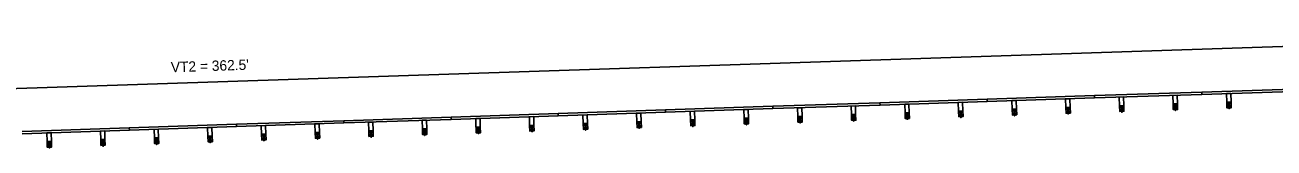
# Model space of a CAD drawing. Extents: x 16537443 to 16538473, y 7054586 to 7055469.
# Drawn here: x 16537667.3 to 16537812.8, y 7054595.8 to 7054610.2 of the extents above; entities that cross this region are included whole.
import ezdxf

# ---------------------------------------------------------------- set-up
doc = ezdxf.new("R2010")
doc.units = 0
doc.layers.add('Draft_DNC', color=7, linetype='Continuous')

msp = doc.modelspace()

# ---------------------------------------------------------------- linework, layer by layer
at = {"layer": 'Draft_DNC'}
for p, q in [((16537888.55, 7054610.16), (16537526.25, 7054598.08)), ((16537779.4, 7054601.52), (16537766.91, 7054601.11)), ((16537791.9, 7054601.94), (16537779.4, 7054601.52)), ((16537779.4, 7054601.52), (16537779.41, 7054601.25)), ((16537779.4, 7054601.52), (16537779.41, 7054601.25)), ((16537791.91, 7054601.67), (16537779.41, 7054601.25)), ((16537782.29, 7054601.35), (16537782.79, 7054601.36)), ((16537782.32, 7054600.35), (16537782.29, 7054601.35)), ((16537782.79, 7054601.36), (16537782.82, 7054600.36)), ((16537788.53, 7054601.56), (16537789.03, 7054601.57)), ((16537788.57, 7054600.55), (16537788.53, 7054601.56)), ((16537789.03, 7054601.57), (16537789.07, 7054600.57)), ((16537804.39, 7054602.35), (16537791.9, 7054601.94)), ((16537791.9, 7054601.94), (16537791.91, 7054601.67)), ((16537791.9, 7054601.94), (16537791.91, 7054601.67)), ((16537804.4, 7054602.08), (16537791.91, 7054601.67)), ((16537794.78, 7054601.76), (16537795.28, 7054601.78)), ((16537794.81, 7054600.76), (16537794.78, 7054601.76)), ((16537795.28, 7054601.78), (16537795.31, 7054600.78)), ((16537801.03, 7054601.97), (16537801.53, 7054601.99)), ((16537801.06, 7054600.97), (16537801.03, 7054601.97)), ((16537801.53, 7054601.99), (16537801.56, 7054600.99)), ((16537816.88, 7054602.77), (16537804.39, 7054602.35)), ((16537804.39, 7054602.35), (16537804.4, 7054602.08)), ((16537804.39, 7054602.35), (16537804.4, 7054602.08)), ((16537816.89, 7054602.5), (16537804.4, 7054602.08)), ((16537807.27, 7054602.18), (16537807.77, 7054602.2)), ((16537807.31, 7054601.18), (16537807.27, 7054602.18)), ((16537807.77, 7054602.2), (16537807.81, 7054601.2)), ((16537741.93, 7054600.27), (16537729.43, 7054599.86)), ((16537741.93, 7054600), (16537729.44, 7054599.58)), ((16537738.56, 7054599.89), (16537739.06, 7054599.91)), ((16537738.59, 7054598.89), (16537738.56, 7054599.89)), ((16537739.06, 7054599.91), (16537739.09, 7054598.91)), ((16537754.42, 7054600.69), (16537741.93, 7054600.27)), ((16537754.43, 7054600.42), (16537741.93, 7054600)), ((16537741.93, 7054600.27), (16537741.93, 7054600)), ((16537741.93, 7054600.27), (16537741.93, 7054600)), ((16537744.81, 7054600.1), (16537745.31, 7054600.11)), ((16537744.84, 7054599.1), (16537744.81, 7054600.1)), ((16537745.31, 7054600.11), (16537745.34, 7054599.11)), ((16537751.05, 7054600.31), (16537751.55, 7054600.32)), ((16537751.09, 7054599.31), (16537751.05, 7054600.31)), ((16537751.55, 7054600.32), (16537751.59, 7054599.32)), ((16537766.91, 7054601.11), (16537754.42, 7054600.69)), ((16537754.42, 7054600.69), (16537754.43, 7054600.42)), ((16537754.42, 7054600.69), (16537754.43, 7054600.42)), ((16537766.92, 7054600.83), (16537754.43, 7054600.42)), ((16537757.3, 7054600.51), (16537757.8, 7054600.53)), ((16537757.33, 7054599.51), (16537757.3, 7054600.51)), ((16537757.8, 7054600.53), (16537757.83, 7054599.53)), ((16537763.55, 7054600.72), (16537764.05, 7054600.74)), ((16537763.58, 7054599.72), (16537763.55, 7054600.72)), ((16537764.05, 7054600.74), (16537764.08, 7054599.74)), ((16537766.91, 7054601.11), (16537766.92, 7054600.83)), ((16537766.91, 7054601.11), (16537766.92, 7054600.83)), ((16537779.41, 7054601.25), (16537766.92, 7054600.83)), ((16537769.79, 7054600.93), (16537770.29, 7054600.95)), ((16537769.83, 7054599.93), (16537769.79, 7054600.93)), ((16537770.33, 7054599.95), (16537769.83, 7054599.93)), ((16537770.35, 7054599.28), (16537769.83, 7054599.93)), ((16537769.85, 7054599.26), (16537770.33, 7054599.95)), ((16537770.08, 7054599.94), (16537770.1, 7054599.27)), ((16537770.29, 7054600.95), (16537770.33, 7054599.95)), ((16537776.04, 7054601.14), (16537776.54, 7054601.16)), ((16537776.07, 7054600.14), (16537776.04, 7054601.14)), ((16537776.57, 7054600.15), (16537776.07, 7054600.14)), ((16537776.6, 7054599.49), (16537776.07, 7054600.14)), ((16537776.1, 7054599.47), (16537776.57, 7054600.15)), ((16537776.32, 7054600.15), (16537776.35, 7054599.48)), ((16537776.54, 7054601.16), (16537776.57, 7054600.15)), ((16537782.82, 7054600.36), (16537782.32, 7054600.35)), ((16537782.84, 7054599.7), (16537782.32, 7054600.35)), ((16537782.34, 7054599.68), (16537782.82, 7054600.36)), ((16537782.57, 7054600.35), (16537782.59, 7054599.69)), ((16537789.07, 7054600.57), (16537788.57, 7054600.55)), ((16537789.09, 7054599.91), (16537788.57, 7054600.55)), ((16537788.59, 7054599.89), (16537789.07, 7054600.57)), ((16537788.82, 7054600.56), (16537788.84, 7054599.9)), ((16537795.31, 7054600.78), (16537794.81, 7054600.76)), ((16537795.34, 7054600.11), (16537794.81, 7054600.76)), ((16537794.84, 7054600.1), (16537795.31, 7054600.78)), ((16537795.06, 7054600.77), (16537795.09, 7054600.11)), ((16537795.09, 7054600.01), (16537795.09, 7054600)), ((16537801.56, 7054600.99), (16537801.06, 7054600.97)), ((16537801.58, 7054600.32), (16537801.06, 7054600.97)), ((16537801.08, 7054600.31), (16537801.56, 7054600.99)), ((16537801.31, 7054600.98), (16537801.33, 7054600.31)), ((16537801.34, 7054600.22), (16537801.34, 7054600.21)), ((16537807.81, 7054601.2), (16537807.31, 7054601.18)), ((16537807.83, 7054600.53), (16537807.31, 7054601.18)), ((16537807.33, 7054600.51), (16537807.81, 7054601.2)), ((16537807.56, 7054601.19), (16537807.58, 7054600.52)), ((16537807.58, 7054600.42), (16537807.58, 7054600.42)), ((16537691.95, 7054598.61), (16537679.46, 7054598.19)), ((16537704.45, 7054599.02), (16537691.95, 7054598.61)), ((16537691.95, 7054598.61), (16537691.96, 7054598.34)), ((16537691.95, 7054598.61), (16537691.96, 7054598.34)), ((16537704.46, 7054598.75), (16537691.96, 7054598.34)), ((16537694.84, 7054598.43), (16537695.34, 7054598.45)), ((16537694.87, 7054597.43), (16537694.84, 7054598.43)), ((16537695.34, 7054598.45), (16537695.37, 7054597.45)), ((16537701.08, 7054598.64), (16537701.58, 7054598.66)), ((16537701.12, 7054597.64), (16537701.08, 7054598.64)), ((16537701.58, 7054598.66), (16537701.62, 7054597.66)), ((16537716.94, 7054599.44), (16537704.45, 7054599.02)), ((16537704.45, 7054599.02), (16537704.46, 7054598.75)), ((16537704.45, 7054599.02), (16537704.46, 7054598.75)), ((16537716.95, 7054599.17), (16537704.46, 7054598.75)), ((16537707.33, 7054598.85), (16537707.83, 7054598.86)), ((16537707.36, 7054597.85), (16537707.33, 7054598.85)), ((16537707.83, 7054598.86), (16537707.86, 7054597.86)), ((16537713.57, 7054599.06), (16537714.07, 7054599.07)), ((16537713.61, 7054598.06), (16537713.57, 7054599.06)), ((16537714.07, 7054599.07), (16537714.11, 7054598.07)), ((16537729.43, 7054599.86), (16537716.94, 7054599.44)), ((16537716.94, 7054599.44), (16537716.95, 7054599.17)), ((16537716.94, 7054599.44), (16537716.95, 7054599.17)), ((16537729.44, 7054599.58), (16537716.95, 7054599.17)), ((16537719.82, 7054599.26), (16537720.32, 7054599.28)), ((16537719.85, 7054598.26), (16537719.82, 7054599.26)), ((16537720.32, 7054599.28), (16537720.35, 7054598.28)), ((16537726.07, 7054599.47), (16537726.57, 7054599.49)), ((16537726.1, 7054598.47), (16537726.07, 7054599.47)), ((16537726.6, 7054598.49), (16537726.1, 7054598.47)), ((16537726.62, 7054597.82), (16537726.1, 7054598.47)), ((16537726.12, 7054597.81), (16537726.6, 7054598.49)), ((16537726.35, 7054598.48), (16537726.37, 7054597.81)), ((16537726.57, 7054599.49), (16537726.6, 7054598.49)), ((16537729.43, 7054599.86), (16537729.44, 7054599.58)), ((16537729.43, 7054599.86), (16537729.44, 7054599.58)), ((16537732.31, 7054599.68), (16537732.81, 7054599.7)), ((16537732.35, 7054598.68), (16537732.31, 7054599.68)), ((16537732.85, 7054598.7), (16537732.35, 7054598.68)), ((16537732.87, 7054598.03), (16537732.35, 7054598.68)), ((16537732.37, 7054598.01), (16537732.85, 7054598.7)), ((16537732.6, 7054598.69), (16537732.62, 7054598.02)), ((16537732.81, 7054599.7), (16537732.85, 7054598.7)), ((16537739.09, 7054598.91), (16537738.59, 7054598.89)), ((16537739.12, 7054598.24), (16537738.59, 7054598.89)), ((16537738.62, 7054598.22), (16537739.09, 7054598.91)), ((16537738.84, 7054598.9), (16537738.87, 7054598.23)), ((16537745.34, 7054599.11), (16537744.84, 7054599.1)), ((16537745.36, 7054598.45), (16537744.84, 7054599.1)), ((16537744.86, 7054598.43), (16537745.34, 7054599.11)), ((16537745.09, 7054599.11), (16537745.11, 7054598.44)), ((16537751.59, 7054599.32), (16537751.09, 7054599.31)), ((16537751.61, 7054598.66), (16537751.09, 7054599.31)), ((16537751.11, 7054598.64), (16537751.59, 7054599.32)), ((16537751.34, 7054599.31), (16537751.36, 7054598.65)), ((16537751.36, 7054598.55), (16537751.36, 7054598.54)), ((16537757.83, 7054599.53), (16537757.33, 7054599.51)), ((16537757.86, 7054598.86), (16537757.33, 7054599.51)), ((16537757.36, 7054598.85), (16537757.83, 7054599.53)), ((16537757.58, 7054599.52), (16537757.61, 7054598.86)), ((16537757.61, 7054598.76), (16537757.61, 7054598.75)), ((16537764.08, 7054599.74), (16537763.58, 7054599.72)), ((16537764.1, 7054599.07), (16537763.58, 7054599.72)), ((16537763.6, 7054599.06), (16537764.08, 7054599.74)), ((16537763.83, 7054599.73), (16537763.85, 7054599.06)), ((16537763.86, 7054598.97), (16537763.86, 7054598.96)), ((16537770.1, 7054599.17), (16537770.1, 7054599.17)), ((16537776.35, 7054599.38), (16537776.35, 7054599.38)), ((16537782.6, 7054599.59), (16537782.6, 7054599.58)), ((16537788.84, 7054599.8), (16537788.84, 7054599.79)), ((16537679.46, 7054598.19), (16537666.97, 7054597.77)), ((16537679.47, 7054597.92), (16537666.98, 7054597.5)), ((16537669.85, 7054597.6), (16537670.35, 7054597.61)), ((16537669.88, 7054596.6), (16537669.85, 7054597.6)), ((16537670.35, 7054597.61), (16537670.38, 7054596.61)), ((16537676.1, 7054597.81), (16537676.6, 7054597.82)), ((16537676.13, 7054596.81), (16537676.1, 7054597.81)), ((16537676.6, 7054597.82), (16537676.63, 7054596.82)), ((16537679.46, 7054598.19), (16537679.47, 7054597.92)), ((16537679.46, 7054598.19), (16537679.47, 7054597.92)), ((16537691.96, 7054598.34), (16537679.47, 7054597.92)), ((16537682.34, 7054598.01), (16537682.84, 7054598.03)), ((16537682.38, 7054597.01), (16537682.34, 7054598.01)), ((16537682.88, 7054597.03), (16537682.38, 7054597.01)), ((16537682.9, 7054596.36), (16537682.38, 7054597.01)), ((16537682.4, 7054596.35), (16537682.88, 7054597.03)), ((16537682.63, 7054597.02), (16537682.65, 7054596.36)), ((16537682.84, 7054598.03), (16537682.88, 7054597.03)), ((16537688.59, 7054598.22), (16537689.09, 7054598.24)), ((16537688.62, 7054597.22), (16537688.59, 7054598.22)), ((16537689.12, 7054597.24), (16537688.62, 7054597.22)), ((16537689.14, 7054596.57), (16537688.62, 7054597.22)), ((16537688.64, 7054596.56), (16537689.12, 7054597.24)), ((16537688.87, 7054597.23), (16537688.89, 7054596.56)), ((16537689.09, 7054598.24), (16537689.12, 7054597.24)), ((16537695.37, 7054597.45), (16537694.87, 7054597.43)), ((16537695.39, 7054596.78), (16537694.87, 7054597.43)), ((16537694.89, 7054596.76), (16537695.37, 7054597.45)), ((16537695.12, 7054597.44), (16537695.14, 7054596.77)), ((16537701.62, 7054597.66), (16537701.12, 7054597.64)), ((16537701.64, 7054596.99), (16537701.12, 7054597.64)), ((16537701.14, 7054596.97), (16537701.62, 7054597.66)), ((16537701.37, 7054597.65), (16537701.39, 7054596.98)), ((16537707.86, 7054597.86), (16537707.36, 7054597.85)), ((16537707.88, 7054597.2), (16537707.36, 7054597.85)), ((16537707.38, 7054597.18), (16537707.86, 7054597.86)), ((16537707.61, 7054597.86), (16537707.63, 7054597.19)), ((16537707.64, 7054597.09), (16537707.64, 7054597.09)), ((16537714.11, 7054598.07), (16537713.61, 7054598.06)), ((16537714.13, 7054597.41), (16537713.61, 7054598.06)), ((16537713.63, 7054597.39), (16537714.11, 7054598.07)), ((16537713.86, 7054598.06), (16537713.88, 7054597.4)), ((16537713.88, 7054597.3), (16537713.88, 7054597.29)), ((16537720.35, 7054598.28), (16537719.85, 7054598.26)), ((16537720.38, 7054597.61), (16537719.86, 7054598.26)), ((16537719.88, 7054597.6), (16537720.35, 7054598.28)), ((16537720.1, 7054598.27), (16537720.13, 7054597.61)), ((16537720.13, 7054597.51), (16537720.13, 7054597.5)), ((16537726.38, 7054597.72), (16537726.38, 7054597.71)), ((16537732.62, 7054597.93), (16537732.62, 7054597.92)), ((16537738.87, 7054598.13), (16537738.87, 7054598.13)), ((16537745.12, 7054598.34), (16537745.12, 7054598.33)), ((16537670.38, 7054596.61), (16537669.88, 7054596.6)), ((16537670.4, 7054595.95), (16537669.88, 7054596.6)), ((16537669.9, 7054595.93), (16537670.38, 7054596.61)), ((16537670.13, 7054596.61), (16537670.15, 7054595.94)), ((16537670.16, 7054595.84), (16537670.16, 7054595.84)), ((16537676.63, 7054596.82), (16537676.13, 7054596.81)), ((16537676.65, 7054596.16), (16537676.13, 7054596.81)), ((16537676.15, 7054596.14), (16537676.63, 7054596.82)), ((16537676.38, 7054596.81), (16537676.4, 7054596.15)), ((16537676.4, 7054596.05), (16537676.4, 7054596.04)), ((16537682.65, 7054596.26), (16537682.65, 7054596.25)), ((16537688.9, 7054596.47), (16537688.9, 7054596.46)), ((16537695.14, 7054596.68), (16537695.14, 7054596.67)), ((16537701.39, 7054596.88), (16537701.39, 7054596.88))]:
    msp.add_line(p, q, dxfattribs=at)
for points in [[(16537770.33, 7054599.95), (16537769.83, 7054599.93), (16537769.85, 7054599.26), (16537770.35, 7054599.28)], [(16537776.57, 7054600.15), (16537776.07, 7054600.14), (16537776.1, 7054599.47), (16537776.6, 7054599.49)], [(16537782.82, 7054600.36), (16537782.32, 7054600.35), (16537782.34, 7054599.68), (16537782.84, 7054599.7)], [(16537789.07, 7054600.57), (16537788.57, 7054600.55), (16537788.59, 7054599.89), (16537789.09, 7054599.91)], [(16537795.31, 7054600.78), (16537794.81, 7054600.76), (16537794.84, 7054600.1), (16537795.34, 7054600.11)], [(16537801.56, 7054600.99), (16537801.06, 7054600.97), (16537801.08, 7054600.31), (16537801.58, 7054600.32)], [(16537807.81, 7054601.2), (16537807.31, 7054601.18), (16537807.33, 7054600.51), (16537807.83, 7054600.53)], [(16537726.6, 7054598.49), (16537726.1, 7054598.47), (16537726.12, 7054597.81), (16537726.62, 7054597.82)], [(16537732.85, 7054598.7), (16537732.35, 7054598.68), (16537732.37, 7054598.01), (16537732.87, 7054598.03)], [(16537739.09, 7054598.91), (16537738.59, 7054598.89), (16537738.62, 7054598.22), (16537739.12, 7054598.24)], [(16537745.34, 7054599.11), (16537744.84, 7054599.1), (16537744.86, 7054598.43), (16537745.36, 7054598.45)], [(16537751.59, 7054599.32), (16537751.09, 7054599.31), (16537751.11, 7054598.64), (16537751.61, 7054598.66)], [(16537757.83, 7054599.53), (16537757.33, 7054599.51), (16537757.36, 7054598.85), (16537757.86, 7054598.86)], [(16537764.08, 7054599.74), (16537763.58, 7054599.72), (16537763.6, 7054599.06), (16537764.1, 7054599.07)], [(16537682.88, 7054597.03), (16537682.38, 7054597.01), (16537682.4, 7054596.35), (16537682.9, 7054596.36)], [(16537689.12, 7054597.24), (16537688.62, 7054597.22), (16537688.64, 7054596.56), (16537689.14, 7054596.57)], [(16537695.37, 7054597.45), (16537694.87, 7054597.43), (16537694.89, 7054596.76), (16537695.39, 7054596.78)], [(16537701.62, 7054597.66), (16537701.12, 7054597.64), (16537701.14, 7054596.97), (16537701.64, 7054596.99)], [(16537707.86, 7054597.86), (16537707.36, 7054597.85), (16537707.38, 7054597.18), (16537707.88, 7054597.2)], [(16537714.11, 7054598.07), (16537713.61, 7054598.06), (16537713.63, 7054597.39), (16537714.13, 7054597.41)], [(16537720.35, 7054598.28), (16537719.86, 7054598.26), (16537719.88, 7054597.6), (16537720.38, 7054597.61)], [(16537670.38, 7054596.61), (16537669.88, 7054596.6), (16537669.9, 7054595.93), (16537670.4, 7054595.95)], [(16537676.63, 7054596.82), (16537676.13, 7054596.81), (16537676.15, 7054596.14), (16537676.65, 7054596.16)]]:
    msp.add_lwpolyline(points, close=True, dxfattribs=at)
for points in [[(16537788.87, 7054599.9), (16537788.87, 7054599.85), (16537788.81, 7054599.85), (16537788.81, 7054599.9)], [(16537795.12, 7054600.11), (16537795.12, 7054600.06), (16537795.05, 7054600.06), (16537795.05, 7054600.1)], [(16537795.11, 7054600.06), (16537795.11, 7054600.01), (16537795.07, 7054600.01), (16537795.07, 7054600.06)], [(16537801.37, 7054600.31), (16537801.37, 7054600.27), (16537801.3, 7054600.27), (16537801.3, 7054600.31)], [(16537801.35, 7054600.27), (16537801.35, 7054600.22), (16537801.32, 7054600.22), (16537801.31, 7054600.27)], [(16537807.61, 7054600.52), (16537807.61, 7054600.48), (16537807.55, 7054600.48), (16537807.55, 7054600.52)], [(16537807.6, 7054600.48), (16537807.6, 7054600.43), (16537807.56, 7054600.42), (16537807.56, 7054600.48)], [(16537745.15, 7054598.44), (16537745.15, 7054598.4), (16537745.08, 7054598.39), (16537745.08, 7054598.44)], [(16537751.39, 7054598.65), (16537751.39, 7054598.61), (16537751.33, 7054598.6), (16537751.33, 7054598.65)], [(16537751.38, 7054598.6), (16537751.38, 7054598.55), (16537751.34, 7054598.55), (16537751.34, 7054598.6)], [(16537757.64, 7054598.86), (16537757.64, 7054598.81), (16537757.57, 7054598.81), (16537757.57, 7054598.85)], [(16537757.63, 7054598.81), (16537757.63, 7054598.76), (16537757.59, 7054598.76), (16537757.59, 7054598.81)], [(16537763.89, 7054599.06), (16537763.89, 7054599.02), (16537763.82, 7054599.02), (16537763.82, 7054599.06)], [(16537763.87, 7054599.02), (16537763.88, 7054598.97), (16537763.84, 7054598.97), (16537763.83, 7054599.02)], [(16537770.13, 7054599.27), (16537770.13, 7054599.23), (16537770.07, 7054599.23), (16537770.07, 7054599.27)], [(16537770.12, 7054599.23), (16537770.12, 7054599.18), (16537770.08, 7054599.17), (16537770.08, 7054599.23)], [(16537776.38, 7054599.48), (16537776.38, 7054599.44), (16537776.31, 7054599.44), (16537776.31, 7054599.48)], [(16537776.37, 7054599.44), (16537776.37, 7054599.38), (16537776.33, 7054599.38), (16537776.33, 7054599.44)], [(16537782.63, 7054599.69), (16537782.63, 7054599.65), (16537782.56, 7054599.64), (16537782.56, 7054599.69)], [(16537782.61, 7054599.65), (16537782.62, 7054599.59), (16537782.58, 7054599.59), (16537782.57, 7054599.64)], [(16537788.86, 7054599.85), (16537788.86, 7054599.8), (16537788.82, 7054599.8), (16537788.82, 7054599.85)], [(16537701.42, 7054596.98), (16537701.42, 7054596.94), (16537701.36, 7054596.94), (16537701.35, 7054596.98)], [(16537707.67, 7054597.19), (16537707.67, 7054597.15), (16537707.6, 7054597.15), (16537707.6, 7054597.19)], [(16537707.65, 7054597.15), (16537707.66, 7054597.09), (16537707.62, 7054597.09), (16537707.62, 7054597.15)], [(16537713.91, 7054597.4), (16537713.92, 7054597.36), (16537713.85, 7054597.35), (16537713.85, 7054597.4)], [(16537713.9, 7054597.36), (16537713.9, 7054597.3), (16537713.86, 7054597.3), (16537713.86, 7054597.35)], [(16537720.16, 7054597.61), (16537720.16, 7054597.56), (16537720.1, 7054597.56), (16537720.09, 7054597.6)], [(16537720.15, 7054597.56), (16537720.15, 7054597.51), (16537720.11, 7054597.51), (16537720.11, 7054597.56)], [(16537726.41, 7054597.82), (16537726.41, 7054597.77), (16537726.34, 7054597.77), (16537726.34, 7054597.81)], [(16537726.39, 7054597.77), (16537726.4, 7054597.72), (16537726.36, 7054597.72), (16537726.36, 7054597.77)], [(16537732.65, 7054598.02), (16537732.65, 7054597.98), (16537732.59, 7054597.98), (16537732.59, 7054598.02)], [(16537732.64, 7054597.98), (16537732.64, 7054597.93), (16537732.6, 7054597.92), (16537732.6, 7054597.98)], [(16537738.9, 7054598.23), (16537738.9, 7054598.19), (16537738.83, 7054598.19), (16537738.83, 7054598.23)], [(16537738.89, 7054598.19), (16537738.89, 7054598.13), (16537738.85, 7054598.13), (16537738.85, 7054598.19)], [(16537745.13, 7054598.4), (16537745.14, 7054598.34), (16537745.1, 7054598.34), (16537745.1, 7054598.4)], [(16537670.19, 7054595.94), (16537670.19, 7054595.9), (16537670.12, 7054595.9), (16537670.12, 7054595.94)], [(16537670.18, 7054595.9), (16537670.18, 7054595.84), (16537670.14, 7054595.84), (16537670.14, 7054595.9)], [(16537676.43, 7054596.15), (16537676.44, 7054596.11), (16537676.37, 7054596.1), (16537676.37, 7054596.15)], [(16537676.42, 7054596.11), (16537676.42, 7054596.05), (16537676.39, 7054596.05), (16537676.38, 7054596.1)], [(16537682.68, 7054596.36), (16537682.68, 7054596.31), (16537682.62, 7054596.31), (16537682.61, 7054596.36)], [(16537682.67, 7054596.31), (16537682.67, 7054596.26), (16537682.63, 7054596.26), (16537682.63, 7054596.31)], [(16537688.93, 7054596.57), (16537688.93, 7054596.52), (16537688.86, 7054596.52), (16537688.86, 7054596.56)], [(16537688.92, 7054596.52), (16537688.92, 7054596.47), (16537688.88, 7054596.47), (16537688.88, 7054596.52)], [(16537695.17, 7054596.77), (16537695.18, 7054596.73), (16537695.11, 7054596.73), (16537695.11, 7054596.77)], [(16537695.16, 7054596.73), (16537695.16, 7054596.68), (16537695.12, 7054596.68), (16537695.12, 7054596.73)], [(16537701.41, 7054596.94), (16537701.41, 7054596.88), (16537701.37, 7054596.88), (16537701.37, 7054596.94)]]:
    msp.add_lwpolyline(points, dxfattribs=at)

# ---------------------------------------------------------------- texts
msp.add_text("VT2 = 362.5'", height=1.2, rotation=1.9106, dxfattribs=at).set_placement((16537684.32, 7054604.65))

doc.saveas('drawing.dxf')
